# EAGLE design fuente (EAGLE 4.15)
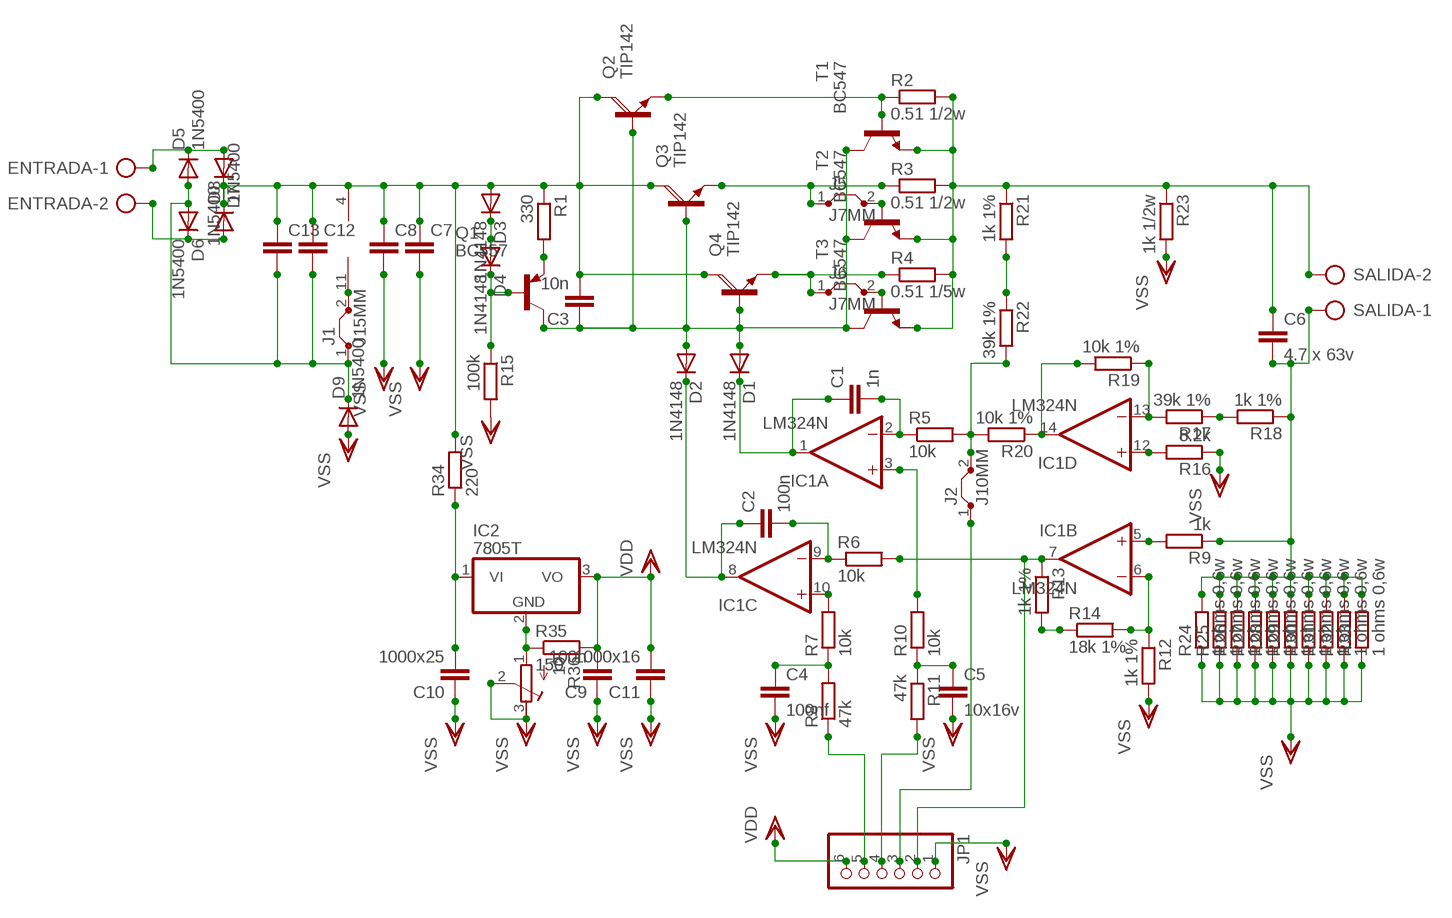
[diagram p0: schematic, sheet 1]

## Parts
C1  1n  C5/2.5  [C5B2.5]
C2  100n  C5/2.5  [C5B2.5]
C3  10n  C5/2.5  [C5B2.5]
C4  100nf  C2.5/6  [C2.5-6]
C5  10x16v  C2.5/6  [C2.5-6]
C6  4.7 x 63v  C5/7.2  [C5B7.2]
C7  C5/7.2  [C5B7.2]
C8  C5/7.2  [C5B7.2]
C9  100n  C5/2.5  [C5B2.5]
C10  1000x25  C7.5/6  [C7.5B6]
C11  1000x16  C7.5/6  [C7.5B6]
C12  C7.5/6  [C7.5B6]
C13  C7.5/6  [C7.5B6]
D1  1N4148  [DO35-10]
D2  1N4148  [DO35-10]
D3  1N4148  [DO35-10]
D4  1N4148  [DO35-10]
D5  1N5400  [DO201-15]
D6  1N5400  [DO201-15]
D7  1N5400  [DO201-15]
D8  1N5400  [DO201-15]
D9  1N5400  [DO201-15]
ENTRADA  AK300/2  [AK300/2]
IC1  LM324N  [DIL14]
IC2  7805T  [TO220H]
J1  J15MM  [15]
J2  J10MM  [10]
J5  J7MM  [07]
J6  J7MM  [07]
JP1  PINHD-1X6  [1X06]
Q1  BC557  [TO92]
Q2  TIP142  [SOT93]
Q3  TIP142  [SOT93]
Q4  TIP142  [SOT93]
R1  330  R-EU_0204/7  [0204/7]
R2  0.51 1/2w  R-EU_0207/12  [0207/12]
R3  0.51 1/2w  R-EU_0207/12  [0207/12]
R4  0.51 1/5w  R-EU_0207/12  [0207/12]
R5  10k  R-EU_0204/7  [0204/7]
R6  10k  R-EU_0204/7  [0204/7]
R7  10k  R-EU_0204/7  [0204/7]
R8  47k  R-EU_0204/7  [0204/7]
R9  1k  R-EU_0204/7  [0204/7]
R10  10k  R-EU_0204/7  [0204/7]
R11  47k  R-EU_0204/7  [0204/7]
R12  1k 1%  R-EU_0204/7  [0204/7]
R13  1k 1%  R-EU_0204/7  [0204/7]
R14  18k 1%  R-EU_0204/7  [0204/7]
R15  100k  R-EU_0204/7  [0204/7]
R16  8.2k  R-EU_0204/7  [0204/7]
R17  39k 1%  R-EU_0204/7  [0204/7]
R18  1k 1%  R-EU_0204/7  [0204/7]
R19  10k 1%  R-EU_0204/7  [0204/7]
R20  10k 1%  R-EU_0204/7  [0204/7]
R21  1k 1%  R-EU_0204/7  [0204/7]
R22  39k 1%  R-EU_0204/7  [0204/7]
R23  1k 1/2w  R-EU_0207/10  [0207/10]
R24  1 ohms 0,6w  R-EU_0207/10  [0207/10]
R25  1 ohms 0,6w  R-EU_0207/10  [0207/10]
R26  1 ohms 0,6w  R-EU_0207/10  [0207/10]
R27  1 ohms 0,6w  R-EU_0207/10  [0207/10]
R28  1 ohms 0,6w  R-EU_0207/10  [0207/10]
R29  1 ohms 0,6w  R-EU_0207/10  [0207/10]
R30  1 ohms 0,6w  R-EU_0207/10  [0207/10]
R31  1 ohms 0,6w  R-EU_0207/10  [0207/10]
R32  1 ohms 0,6w  R-EU_0207/10  [0207/10]
R33  1 ohms 0,6w  R-EU_0207/10  [0207/10]
R34  220  R-EU_0207/10  [0207/10]
R35  150  R-EU_0204/7  [0204/7]
R36  10  R-TRIMM64Z  [RTRIM64Z]
SALIDA  AK300/2  [AK300/2]
T1  BC547  [TO92]
T2  BC547  [TO92]
T3  BC547  [TO92]

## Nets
N$1: Q2.E R2.1 T1.2(B)
N$2: J5.1 Q3.E R3.1
N$3: J6.1 Q4.E R4.1
N$4: C3.1 D1.A D2.A Q1.3(C) Q2.B Q3.B Q4.B T1.3(C) T2.3(C) T3.3(C)
N$5: JP1.5 R8.1
N$6: C6.1 R2.2 R3.2 R4.2 R21.1 R23.1 SALIDA.2 T1.1(E) T2.1(E) T3.1(E)
N$7: Q1.1(E) R1.2
N$8: R21.2 R22.1
N$9: R17.1 R18.2
N$10: IC1.14(D:OUT) R19.2 R20.1
N$11: IC1.13(D:-IN) R17.2 R19.1
N$12: IC1.12(D:+IN) R16.2
N$13: J2.1 JP1.3
N$14: C1.1 D1.C IC1.1(A:OUT)
N$15: C1.2 IC1.2(A:-IN) R5.1
N$16: IC1.3(A:+IN) R10.2
N$17: C5.1 R10.1 R11.1
N$18: IC1.10(C:+IN) R7.2
N$19: C4.1 R7.1 R8.2
N$20: C2.2 IC1.9(C:-IN) R6.1
N$21: C2.1 D2.C IC1.8(C:OUT)
N$22: IC1.5(B:+IN) R9.2
N$23: R13.2 R14.1
N$24: IC1.6(B:-IN) R12.1 R14.2
N$25: IC1.7(B:OUT) JP1.2 R6.2 R13.1
N$26: D3.C D4.A
N$27: C6.2 R9.1 R18.1 R24.2 R25.2 R26.2 R27.2 R28.2 R29.2 R30.2 R31.2 R32.2 R33.2 SALIDA.1
N$28: D4.C Q1.2(B) R15.1
N$29: IC1.11(P:V-) J1.2
N$30: C10.2 IC2.1(VI) R34.1
N$31: IC2.2(GND) R35.1 R36.1(E)
N$32: JP1.4 R11.2
N$34: D5.C D7.A ENTRADA.1
N$35: D6.C D8.A ENTRADA.2
N$36: C12.2 C13.2 D5.A D6.A D9.C J1.1
N$37: C3.2 C7.1 C8.1 C12.1 C13.1 D3.A D7.C D8.C IC1.4(P:V+) Q2.C Q3.C Q4.C R1.1 R34.2
N$38: J2.2 R5.2 R20.2 R22.2
N$40: J5.2 T2.2(B)
N$41: J6.2 T3.2(B)
VDD: C9.2 C11.2 IC2.3(VO) JP1.6 R35.2
VSS: C4.2 C5.2 C7.2 C8.2 C9.1 C10.1 C11.1 D9.A JP1.1 R12.2 R15.2 R16.1 R23.2 R24.1 R25.1 R26.1 R27.1 R28.1 R29.1 R30.1 R31.1 R32.1 R33.1 R36.2(S) R36.3(A)

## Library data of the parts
C1-C13 = capacitor-wima:C: CAPACITOR
D1-D4 = diode:1N4148: DIODE
D5-D9 = diode:1N5400: DIODE
ENTRADA SALIDA = con-ptr500:AK300/2: CONNECTOR
IC1 = linear:LM324: OP AMP
IC2 = linear:78*: Positive VOLTAGE REGULATOR Source: http://cache.national.com/ds/LM/LM78L05.pdf http://www.fairchildsemi.com/ds/LM/LM7805.pdf
J1 J2 J5 J6 = jumper:J: Bridge
JP1 = pinhead:PINHD-1X6: PIN HEADER
Q1 = transistor-pnp:BC557: PNP Transistor
Q2-Q4 = transistor-power:TIP142: NPN DARLINGTON TRANSISTOR
R1-R35 = rcl:R-EU_: RESISTOR, European symbol
R36 = rcl:R-TRIMM: Trimm resistor
T1-T3 = transistor:BC547: NPN TRANSISTOR

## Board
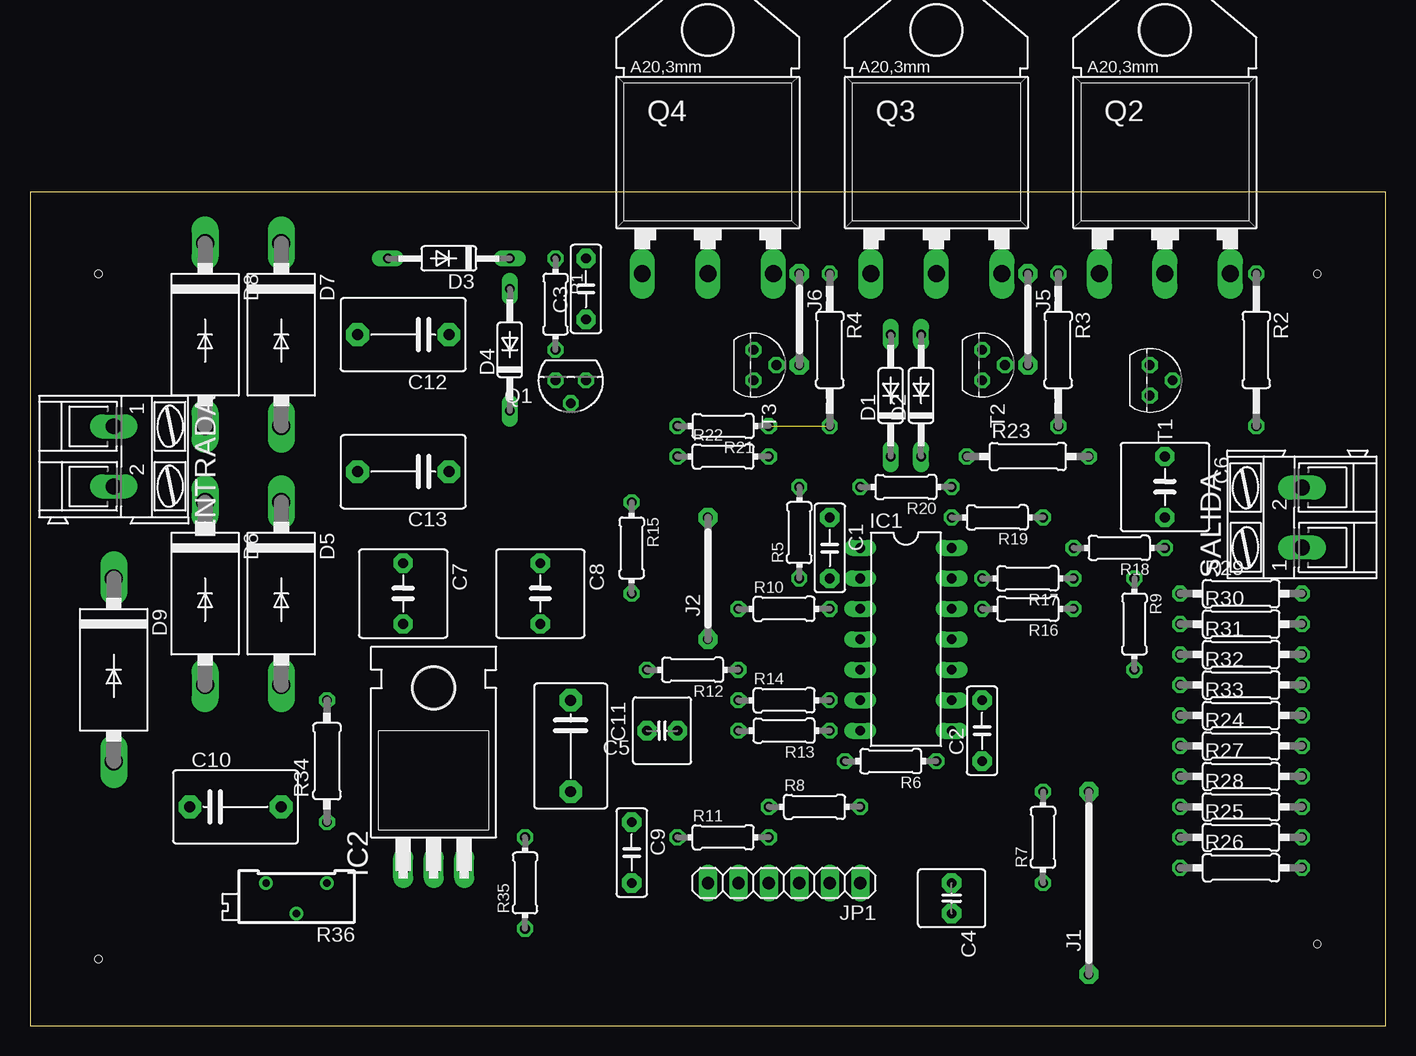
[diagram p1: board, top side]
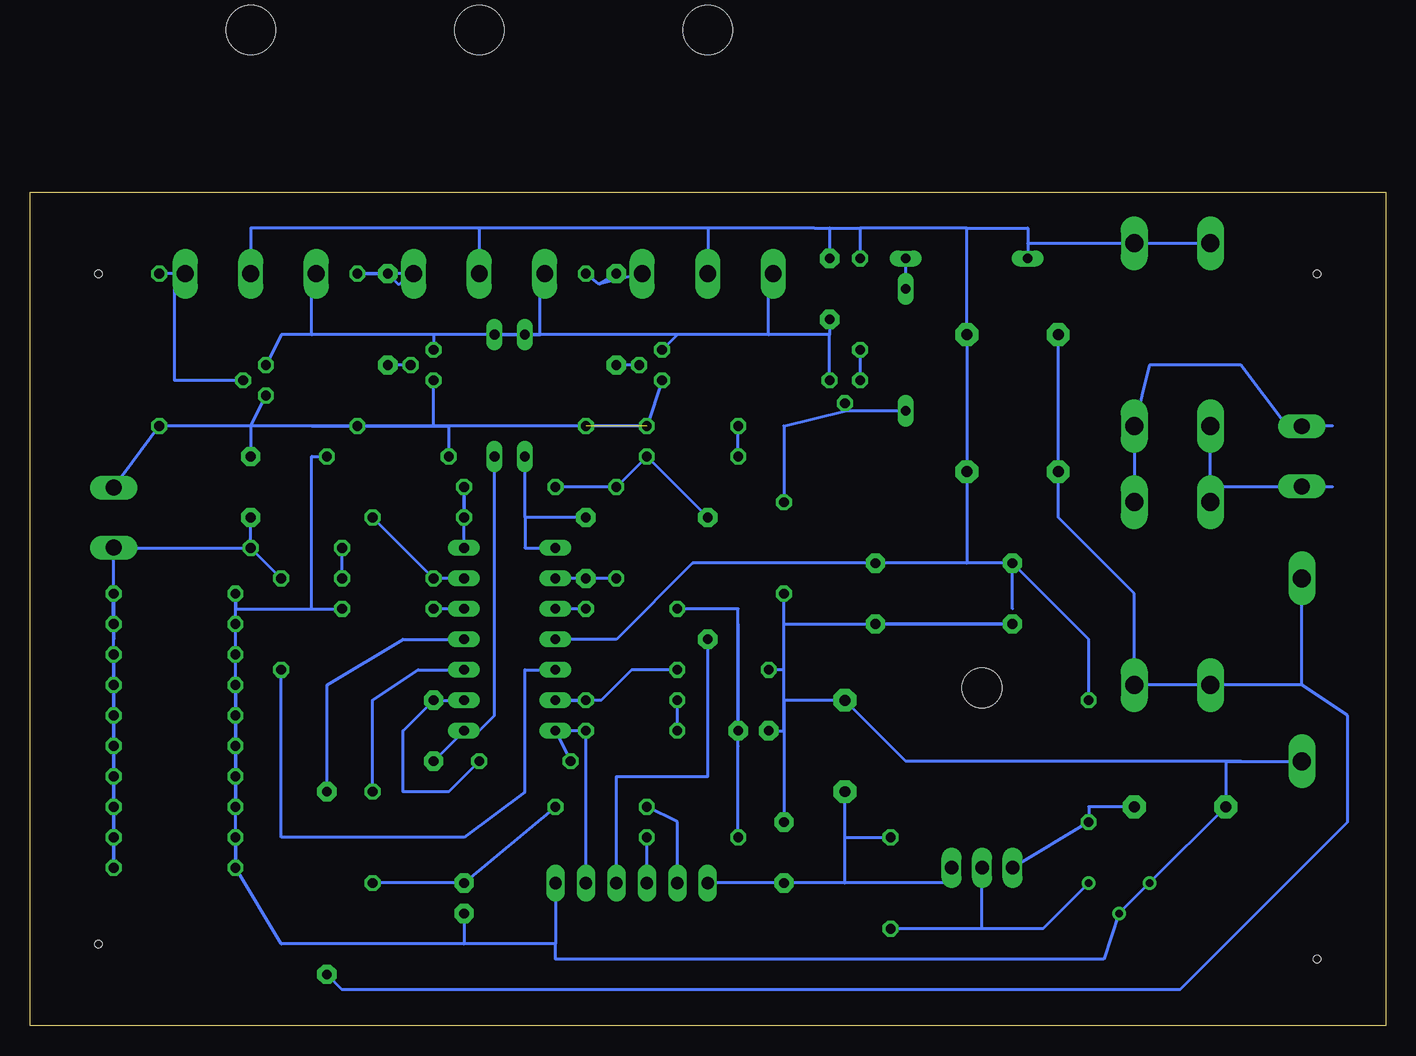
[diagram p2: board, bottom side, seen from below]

Size 113.01 x 69.52 mm. Coordinates in mm from the lower left corner, seen from the top.
Outline: 0,0 113.01,0 113.01,69.52 0,69.52 0,0
Copper layers (1*16): Top 0.035mm / dielectric 1.5mm / Bottom 0.035mm
Design rules "default": minimum track width 10mil, minimum drill 24mil, track to track 8mil, track to pad 8mil, pad to pad 8mil, via to via 8mil, smd to smd 8mil, copper to edge 40mil, drill to drill 8mil, minimum pad ring 10mil, minimum via ring 8mil, stop-mask expansion 4mil, vias tented up to drill 0mil, thermal gap 10mil
Holes 0.6 mm at 5.71,62.7 5.71,5.55 107.31,6.82 107.31,62.7

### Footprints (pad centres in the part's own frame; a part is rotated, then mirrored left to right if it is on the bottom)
C5B2.5 = drill 0.813 pad 1.6 octagon: 1 -2.54,0; 2 2.54,0
C2.5-6 = drill 0.813 pad 1.6 octagon: 1 -1.27,0; 2 1.27,0
C5B7.2 = drill 0.813 pad 1.6 octagon: 1 -2.54,0; 2 2.54,0
C7.5B6 = drill 0.914 pad 1.905 octagon: 1 -3.81,0; 2 3.81,0
DO35-10 = drill 0.813 long: A 5.08,0; C -5.08,0
DO201-15 = drill 1.499 long: A 7.62,0; C -7.62,0
AK300/2 = drill 1.321 long: 1 -2.515,0; 2 2.489,0
DIL14 = drill 0.813 long: 1 -7.62,-3.81; 2 -5.08,-3.81; 3 -2.54,-3.81; 4 0,-3.81; 5 2.54,-3.81; 6 5.08,-3.81; 7 7.62,-3.81; 8 7.62,3.81; 9 5.08,3.81; 10 2.54,3.81; 11 0,3.81; 12 -2.54,3.81; 13 -5.08,3.81; 14 -7.62,3.81
TO220H = drill 1.118 long: 1 -2.54,-10.16; 2 0,-10.16; 3 2.54,-10.16 | hole 3.302: 0,4.826
15 = drill 0.813 pad 1.6 octagon: 1 -7.62,0; 2 7.62,0
10 = drill 0.813 pad 1.6 octagon: 1 -5.08,0; 2 5.08,0
07 = drill 0.813 pad 1.6 octagon: 1 -3.81,0; 2 3.81,0
1X06 = drill 1.016 long: 1 -6.35,0; 2 -3.81,0; 3 -1.27,0; 4 1.27,0; 5 3.81,0; 6 6.35,0
TO92 = drill 0.813 octagon: 1 1.27,0; 2 0,1.905; 3 -1.27,0
SOT93 = drill 1.397 long: B -5.461,-10.16; C 0,-10.16; E 5.461,-10.16 | hole 4.115: 0,10.16
0204/7 = drill 0.813 octagon: 1 -3.81,0; 2 3.81,0
0207/12 = drill 0.813 octagon: 1 -6.35,0; 2 6.35,0
0207/10 = drill 0.813 octagon: 1 -5.08,0; 2 5.08,0
RTRIM64Z = drill 0.61 round: 1 0,-2.54; 2 -2.54,0; 3 0,2.54

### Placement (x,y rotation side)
C1  66.67,39.84 270 top
C2  79.37,24.6 90 top
C3  46.35,61.43 90 top
C4  76.83,10.63 270 top
C5  52.7,24.6 180 top
C6  94.61,44.92 270 top
C7  31.11,36.03 270 top
C8  42.54,36.03 270 top
C9  50.16,14.44 270 top
C10  17.14,18.25 0 top
C11  45.08,23.33 270 top
C12  31.11,57.62 180 top
C13  31.11,46.19 180 top
D1  71.75,52.54 90 top
D2  74.29,52.54 90 top
D3  34.92,63.97 180 top
D4  40,56.35 90 top
D5  20.95,36.03 270 top
D6  14.6,36.03 270 top
D7  20.95,57.62 270 top
D8  14.6,57.62 270 top
D9  6.98,29.68 270 top
ENTRADA  6.98,47.46 270 top
IC1  73.02,32.22 270 top
IC2  33.65,23.33 0 top
J1  88.26,11.9 90 top
J2  56.51,37.3 90 top
J5  83.18,58.89 270 top
J6  64.13,58.89 270 top
JP1  62.86,11.9 180 top
Q1  45.08,53.81 180 top
Q2  94.61,72.86 0 top
Q3  75.56,72.86 0 top
Q4  56.51,72.86 0 top
R1  43.81,60.16 270 top
R2  102.23,56.35 270 top
R3  85.72,56.35 270 top
R4  66.67,56.35 270 top
R5  64.13,41.11 90 top
R6  71.75,22.06 180 top
R7  84.45,15.71 90 top
R8  65.4,18.25 0 top
R9  92.07,33.49 270 top
R10  62.86,34.76 0 top
R11  57.78,15.71 0 top
R12  55.24,29.68 180 top
R13  62.86,24.6 180 top
R14  62.86,27.14 0 top
R15  50.16,39.84 270 top
R16  83.18,34.76 180 top
R17  83.18,37.3 180 top
R18  90.8,39.84 180 top
R19  80.64,42.38 180 top
R20  73.02,44.92 180 top
R21  57.78,50 180 top
R22  57.78,47.46 0 top
R23  83.18,47.46 0 top
R24  100.96,23.33 0 top
R25  100.96,15.71 0 top
R26  100.96,13.17 0 top
R27  100.96,20.79 0 top
R28  100.96,18.25 0 top
R29  100.96,36.03 0 top
R30  100.96,33.49 0 top
R31  100.96,30.95 0 top
R32  100.96,28.41 0 top
R33  100.96,25.87 0 top
R34  24.76,22.06 90 top
R35  41.27,11.9 90 top
R36  22.22,11.9 90 top
SALIDA  106.04,42.38 90 top
T1  93.34,53.81 270 top
T2  79.37,55.08 270 top
T3  60.32,55.08 270 top

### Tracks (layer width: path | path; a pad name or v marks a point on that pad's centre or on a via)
N$1
  Bottom 0.254: Q2.E R2.1 | Q2.E R2.1 | Q2.E R2.1 | T1.2 100.96,53.81 100.96,62.7 Q2.E
N$2
  Bottom 0.254: Q3.E R3.1 | Q3.E R3.1 | R3.1 J5.1 | Q3.E 82.29,61.81 J5.1 | J5.1 R3.1
N$3
  Bottom 0.254: Q4.E 65.55,61.84 | 65.55,61.84 R4.1 | 65.55,61.84 J6.1
N$4
  Bottom 0.254: 89.53,57.62 92.07,57.62 T1.3 | Q1.3 46.35,57.62 | 59.05,57.62 T3.3 | 51.43,57.62 51.43,62.7 Q4.B | C3.1 46.35,57.62 | 46.35,57.62 51.43,57.62 | 51.43,57.62 59.05,57.62 | 59.05,57.62 70.48,57.62 | 70.48,57.62 D1.A D2.A | D2.A 70.48,57.62 | 70.48,57.62 70.48,62.7 Q3.B | 89.53,57.62 89.53,61.43 Q2.B | 79.37,57.62 89.53,57.62 | D2.A 79.37,57.62 | 79.37,57.62 T2.3
N$5
  Bottom 0.254: JP1.5 59.05,16.98 R8.1
N$6  (1 unrouted)
  Bottom 0.254: T3.1 R21.1 79.37,50 | 79.37,50 T2.1 | 94.61,50 T1.1 | 89.53,50 79.37,50 | 79.37,50 78.1,50 R23.1 | SALIDA.2 R2.2 94.61,50 | 94.61,50 C6.1 | 79.37,50 R3.2 89.53,50 | 89.53,50 94.61,50
N$7
  Bottom 0.254: R1.2 Q1.1
N$8
  Bottom 0.254: R22.1 R21.2
N$9
  Bottom 0.254: R17.1 R18.2
N$10
  Bottom 0.254: R20.1 IC1.14 R20.1 | R20.1 R19.2
N$11
  Bottom 0.254: IC1.13 R17.2 R19.1
N$12
  Bottom 0.254: IC1.12 R16.2
N$13
  Bottom 0.254: J2.1 56.51,20.79 64.13,20.79 JP1.3
N$14
  Bottom 0.254: 71.75,42.38 71.75,39.84 IC1.1 | C1.1 71.75,42.38 | 71.75,42.38 D1.C
N$15
  Bottom 0.254: R5.1 C1.2 IC1.2
N$16
  Bottom 0.254: R10.2 IC1.3
N$17
  Bottom 0.254: R11.1 53.97,33.49 | R10.1 53.97,34.76 53.97,33.49 | 53.97,33.49 C5.1 53.97,23.33
N$18
  Bottom 0.254: IC1.10 80.64,29.68 84.45,27.14 R7.2
N$19
  Bottom 0.254: R8.2 C4.1 R7.1
N$20
  Bottom 0.254: R6.1 78.1,19.52 81.91,19.52 81.91,24.6 C2.2 IC1.9
N$21
  Bottom 0.254: C2.1 IC1.8 75.56,24.6 74.29,25.87 D2.C
N$22
  Bottom 0.254: R9.2 92.07,15.71 76.83,15.71 71.75,19.52 71.75,29.68 IC1.5
N$23
  Bottom 0.254: R13.2 R14.1
N$24
  Bottom 0.254: R14.2 IC1.6 65.4,27.14 62.86,29.68 R12.1
N$25
  Bottom 0.254: R6.2 IC1.7 R13.1 JP1.2
N$26
  Bottom 0.254: D4.A D3.C
N$27
  Bottom 0.254: R29.2 R30.2 106.04,32.22 106.06,36.05 | R31.2 R32.2 R33.2 R24.2 R27.2 R28.2 R25.2 R26.2 R31.2 | 106.06,33.52 106.01,33.52 106.04,39.84 | 106.04,39.84 SALIDA.1 | R18.1 C6.2 | R9.1 R18.1 | R31.2 R29.2 | R29.2 106.04,39.84 | 106.04,39.84 R18.1
N$28
  Bottom 0.254: R15.1 50.16,50 45.08,51.27 | D4.C 45.08,51.27 | 45.08,51.27 Q1.2
N$29
  Bottom 0.254: J1.2 88.26,28.41 81.91,32.22 IC1.11
N$30
  Bottom 0.254: C10.2 24.76,18.25 R34.1 IC2.1
N$31
  Bottom 0.254: 33.65,8.09 R35.1 | R36.1 28.57,8.09 33.65,8.09 | 33.65,8.09 IC2.2
N$32
  Bottom 0.254: JP1.4 R11.2
N$34
  Bottom 0.254: ENTRADA.1 4.44,50 8.25,50 12.06,55.08 19.68,55.08 D7.A D5.C
N$35
  Bottom 0.254: 14.6,44.92 4.44,44.92 ENTRADA.2 | 14.6,44.92 D8.A | 14.6,44.92 D6.C
N$36
  Bottom 0.254: C12.2 C13.2 27.3,42.38 20.95,36.03 D5.A | D6.A D5.A | D6.A D5.A | J1.1 86.99,3.01 17.14,3.01 3.17,16.98 3.17,25.87 6.98,28.41 | 6.98,28.41 D6.A | 6.98,28.41 D9.C
N$37
  Bottom 0.254: 31.11,34.76 C7.1 | R34.2 24.76,32.22 C7.1 | C7.1 34.92,38.57 | 29.84,65.24 D7.C D8.C | 34.92,66.51 43.81,66.51 | 34.92,66.51 C12.1 C13.1 34.92,38.57 | 34.92,66.51 29.84,66.51 29.84,65.24 | 29.84,65.24 D3.A | 75.56,66.51 94.61,66.51 Q2.C | 34.92,38.57 C8.1 57.78,38.57 64.13,32.22 IC1.4 | 47.62,66.51 56.51,66.51 | 47.62,66.51 46.35,66.51 C3.2 | 47.62,66.51 43.81,66.51 | 43.81,66.51 R1.1 | 56.51,66.51 75.56,66.51 | 75.56,66.51 Q3.C | 56.51,66.51 Q4.C
N$38
  Bottom 0.254: R20.2 R5.2 R22.2 J2.2
N$40
  Bottom 0.254: T2.2 J5.2
N$41
  Bottom 0.254: T3.2 J6.2
VDD
  Bottom 0.254: IC2.3 36.19,11.9 45.08,11.9 | 45.08,15.71 C11.2 | 45.08,11.9 C9.2 JP1.6 | 45.08,11.9 45.08,15.71 | 45.08,15.71 R35.2
VSS
  Bottom 0.254: 89.53,34.76 89.53,47.46 R23.2 | R30.1 R29.1 | R32.1 R31.1 | R25.1 R26.1 | R32.1 R27.1 R24.1 R33.1 R32.1 | R32.1 R28.1 | R25.1 R28.1 | R28.1 R32.1 | R25.1 R26.1 | R25.1 R26.1 | R25.1 R28.1 | R31.1 R30.1 | R31.1 R30.1 | R30.1 R29.1 | R30.1 R29.1 | R30.1 R29.1 | R30.1 R29.1 | R29.1 95.88,34.76 89.53,34.76 | 89.53,34.76 R16.1 | R31.1 R30.1 | 50.16,27.14 C9.1 | C8.2 C7.2 50.16,33.49 | 50.16,27.14 C11.1 40,22.06 12.06,22.06 | 50.16,27.14 50.16,24.6 | C5.2 50.16,24.6 | 50.16,24.6 50.16,33.49 | 50.16,33.49 R15.2 | 12.06,22.06 13.33,22.06 C10.1 R36.3 R36.2 23.49,5.55 69.21,5.55 69.21,6.82 | 12.06,22.06 D9.A | 50.16,27.14 50.16,29.68 R12.2 | JP1.1 69.21,6.82 | 69.21,6.82 76.83,6.82 | C4.2 76.83,6.82 | 76.83,6.82 92.07,6.82 R26.1 | R26.1 R25.1 | R25.1 R26.1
